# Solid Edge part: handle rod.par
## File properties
Title: Handle Rod
Author: Abhinav Rai
Template: Normal.par
Last saved by: Cadcim
Revision: 7
Application: Solid Edge
Density: 0.0000078 kg/mm^3
Accuracy: 0.01
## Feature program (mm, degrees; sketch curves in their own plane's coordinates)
sketch for "unnamed Protrusion 1" plane through (0, 0, 0) normal (0, -1, 0) x-axis (1, 0, 0)
  circle centre (0, 0) radius 3.9624
extrude "unnamed Protrusion 1" add finite 130.175 symmetric
sketch for "ExtrudedCutout_1" plane through (0, 0, 0) normal (0, 0, 1) x-axis (1, 0, 0)
  circle centre (0, 57.4675) radius 1.905
extrude "ExtrudedCutout_1" cut finite 101.6 symmetric
mirror "unnamed Mirror 1" of "ExtrudedCutout_1"
pattern "unnamed Pattern 1"
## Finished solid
Body 1: solid body, 5 faces, 6 edges, 0 vertices.
  Faces by surface: cylinder 3, plane 2
  Edges by curve: intersection 4, circle 2
Bounding box of the edges (mm): 7.925 x 130.175 x 7.925, from (-3.9624, -65.0875, -3.9624) to (3.9624, 65.0875, 3.9624).
Cylindrical faces by radius (mm): R1.905 x2, R3.9624 x1
Planar faces by outward normal: +y 1, -y 1
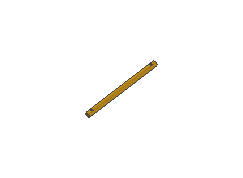
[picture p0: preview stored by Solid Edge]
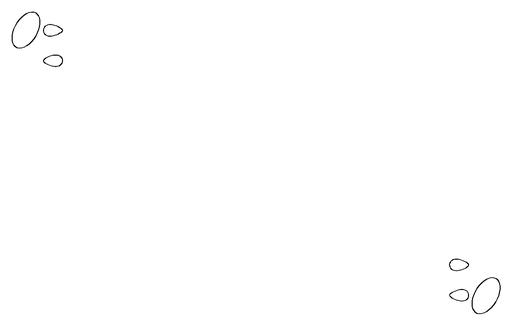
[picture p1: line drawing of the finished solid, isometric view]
